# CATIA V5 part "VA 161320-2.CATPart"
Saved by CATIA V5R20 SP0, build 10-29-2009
Part number: VA 161320-2
Revision: ANY
Definition: UNKNOWN
Nomenclature: VA 161320-2
Source: Unknown
Bounding box of the stored display mesh (mm): x -8 to 8, y 0 to 20, z -8 to 8
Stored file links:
  C:\Users\Utente\Desktop\IO LAVORO\3D X SITO CF\CUMSA\3D files VA\VA 161320\VA 161320-2.CATPart
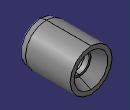
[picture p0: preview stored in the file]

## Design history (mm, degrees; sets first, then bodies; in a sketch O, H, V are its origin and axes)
Body1 "Redondeo1" (main body)
  Solid1: solid without history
